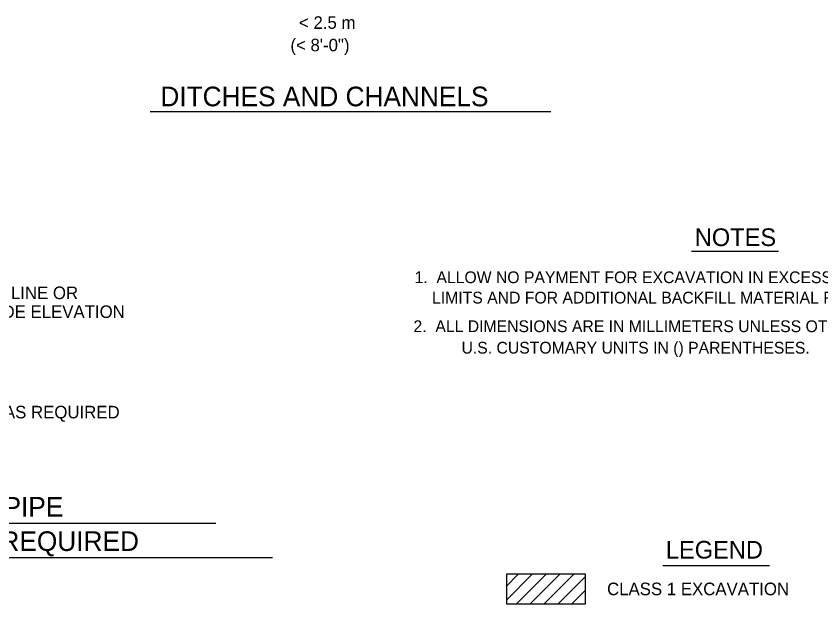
# Model space of a CAD drawing. Extents: x 240 to 1147, y 662 to 1256.
# Drawn here: x 760.7 to 965.7, y 956.6 to 1106.4 of the extents above; entities that cross this region are included whole.
import ezdxf

# ---------------------------------------------------------------- set-up
doc = ezdxf.new("R2010")
doc.units = 0
for name, color, linetype in [('1', 7, 'Continuous'), ('2', 7, 'Continuous'), ('3', 7, 'Continuous')]:
    doc.layers.add(name, color=color, linetype=linetype)

msp = doc.modelspace()

# ---------------------------------------------------------------- linework, layer by layer
at = {"layer": '2'}
for p, q in [((794.829, 1082.044875), (896.88725, 1082.044875)), ((954.9385, 1046.416875), (932.71425, 1046.416875)), ((615.55375, 977.152875), (811.5685, 977.152875)), ((601.731, 968.477875), (825.97875, 968.477875)), ((952.615125, 966.31625), (925.431875, 966.31625)), ((885.581625, 957.58925), (892.150375, 964.158)), ((885.581625, 961.1245), (888.614875, 964.158)), ((888.150375, 956.6225), (895.685875, 964.158)), ((891.685875, 956.6225), (899.221125, 964.158)), ((895.221125, 956.6225), (902.756625, 964.158)), ((898.756625, 956.6225), (905.779625, 963.6455)), ((902.292125, 956.6225), (905.779625, 960.11))]:
    msp.add_line(p, q, dxfattribs=at)
msp.add_lwpolyline([(905.779625, 964.158), (885.581625, 964.158), (885.581625, 956.6225), (905.779625, 956.6225)], close=True, dxfattribs=at)

# ---------------------------------------------------------------- texts
at = {"layer": '1'}
for s, height, p in [('(< 8\'-0")', 3.1999995, (830.58125, 1097.414875)), ('1.  ALLOW NO PAYMENT FOR EXCAVATION IN EXCESS OF SPECIFIED', 3, (862.20075, 1038.346125)), ('    LIMITS AND FOR ADDITIONAL BACKFILL MATERIAL REQUIRED.', 3, (862.20075, 1033.158625)), ('EXCAVATION FOR REMOVAL OF EXISTING PIPE', 4.9999995, (617.81625, 978.861375)), ('OR STRUCTURE WHERE NO REPLACEMENT IS REQUIRED', 4.9999995, (602.91625, 970.111375))]:
    msp.add_text(s, height=height, dxfattribs=at).set_placement(p)
at = {"layer": '2'}
for s, height, p in [('2.  ALL DIMENSIONS ARE IN MILLIMETERS UNLESS OTHERWISE NOTED.', 3, (861.93275, 1025.866739)), ('U.S. CUSTOMARY UNITS IN () PARENTHESES.', 3, (874.158979, 1020.397475)), ('DEPTH, AS REQUIRED', 3.1999875, (740.7225, 1003.894625))]:
    msp.add_text(s, height=height, dxfattribs=at).set_placement(p)
at = {"layer": '3'}
for s, height, p in [('< 2.5 m', 3.1999995, (832.758, 1103.142625)), ('DITCHES AND CHANNELS', 4.9998615, (797.45175, 1083.413625)), ('NOTES', 4.5, (933.583, 1047.800125)), ('GROUND LINE OR', 3.1999875, (739.1725, 1034.275875)), ('SUBGRADE ELEVATION', 3.1999875, (739.1725, 1029.475875)), ('LEGEND', 4.5, (926.206625, 968.1705)), ('CLASS 1 EXCAVATION', 3.1999875, (911.237875, 958.84325))]:
    msp.add_text(s, height=height, dxfattribs=at).set_placement(p)

doc.saveas('drawing.dxf')
